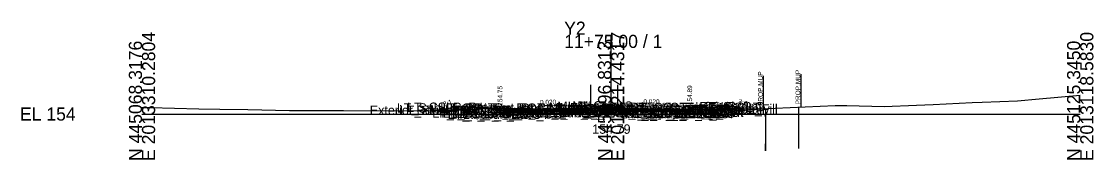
# Model space of a CAD drawing. Extents: x -26 to 203, y -10 to 6017.
# Drawn here: x -25.7 to 202.8, y 3490.3 to 3519.7 of the extents above; entities that cross this region are included whole.
import ezdxf

# ---------------------------------------------------------------- set-up
doc = ezdxf.new("R2010")
doc.units = 0
for name, color, linetype in [('Default', 7, 'Continuous'), ('Exist CMT Pavement', 7, 'Continuous'), ('Exist Cross Section Cell', 7, 'Continuous'), ('Exist XS Center Line Elevation Label', 7, 'Continuous'), ('Exist XS Ground Line', 7, 'Continuous'), ('Prop CMT Conc Surface', 7, 'Continuous'), ('Prop CMT Concrete Structures', 7, 'Continuous'), ('Prop CMT Pvmt Course 1', 7, 'Continuous'), ('Prop CMT Pvmt Course 1 CG', 7, 'Continuous'), ('Prop CMT Pvmt Course 1 Wedge', 7, 'Continuous'), ('Prop CMT Pvmt Course 2', 7, 'Continuous'), ('Prop CMT Pvmt Course 2 Wedge', 7, 'Continuous'), ('Prop CMT Pvmt Course 3', 7, 'Continuous'), ('Prop CMT Pvmt Surface', 7, 'Continuous'), ('Prop CMT Pvmt Wedge Surface 1', 7, 'Continuous'), ('Prop CMT Pvmt Wedge Surface 2', 7, 'Continuous'), ('Prop CMT Pvmt Wedge Surface 3', 7, 'Continuous'), ('Prop CMT Slope Grass', 7, 'Continuous'), ('Prop CMT Subgrade Earthwork', 7, 'Continuous'), ('Prop XS Earthwork Shape', 7, 'Continuous'), ('Prop XS Hydro Elevations', 7, 'Continuous'), ('Prop XS Label Text', 7, 'Continuous'), ('Prop XS SE Text', 7, 'Continuous'), ('Prop XS Side Slope Text', 7, 'Continuous'), ('Scratch_Level_0', 7, 'Continuous'), ('Scratch_Level_1', 7, 'Continuous'), ('Scratch_Level_3', 7, 'Continuous')]:
    doc.layers.add(name, color=color, linetype=linetype)

msp = doc.modelspace()

# ---------------------------------------------------------------- linework, layer by layer
at = {"layer": 'Exist CMT Pavement'}
msp.add_lwpolyline([(96.81, 3500.8), (100, 3500.79), (106.16, 3500.78), (106.96, 3500.77), (107.67, 3500.77), (113.75, 3500.75)], dxfattribs=at)
at = {"layer": 'Exist Cross Section Cell'}
for p, q in [((100, 3500), (100, 3516.87)), ((0, 3500), (100, 3500)), ((100, 3500), (200, 3500))]:
    msp.add_line(p, q, dxfattribs=at)
at = {"layer": 'Exist XS Ground Line'}
msp.add_lwpolyline([(0, 3501.37), (1.74, 3501.42), (12.12, 3501.1), (16.59, 3501.03), (22.55, 3500.95), (31.45, 3500.78), (32.99, 3500.74), (36.63, 3500.73), (41.86, 3500.72), (42.97, 3500.72), (54.75, 3500.66), (55.19, 3500.66), (61.72, 3500.74), (66.6, 3500.85), (74.03, 3501.16), (74.73, 3501.17), (82.07, 3501.15), (89, 3501.08), (92.28, 3501.08), (94.96, 3501.08), (95.27, 3501.03), (96.81, 3500.8), (100, 3500.79), (106.16, 3500.78), (106.96, 3500.77), (107.67, 3500.77), (116.6, 3500.73), (118.47, 3500.97), (119.47, 3500.97), (124.15, 3501.08), (130.91, 3501.08), (131.78, 3501.11), (147.77, 3501.82), (150.27, 3501.82), (158.2, 3501.62), (165.12, 3501.92), (168.63, 3502.05), (176.93, 3502.43), (179.07, 3502.52), (186.62, 3502.78), (191.27, 3503.25), (200, 3504.03)], dxfattribs=at)
at = {"layer": 'Prop CMT Conc Surface'}
for points in [[(76.33, 3500.75), (76.33, 3501.25), (75.83, 3501.25)], [(116.77, 3500.89), (116.77, 3501.39), (117.27, 3501.39)], [(78.33, 3500.87), (76.33, 3500.75)], [(114.77, 3501.01), (116.77, 3500.89)]]:
    msp.add_lwpolyline(points, dxfattribs=at)
at = {"layer": 'Prop CMT Concrete Structures'}
for p, q in [((95.72, 3501.38), (95.71, 3501.22)), ((96.47, 3501.63), (95.72, 3501.38)), ((98.91, 3501.73), (96.47, 3501.63)), ((100.7, 3501.69), (98.91, 3501.73)), ((101.45, 3501.44), (100.7, 3501.69)), ((101.46, 3501.27), (101.45, 3501.44))]:
    msp.add_line(p, q, dxfattribs=at)
for points in [[(78.33, 3500.87), (76.33, 3500.75), (76.33, 3501.25), (75.83, 3501.25)], [(75.83, 3501.25), (75.83, 3500.24), (78.33, 3500.29)], [(95.71, 3501.22), (101.46, 3501.27)], [(114.77, 3501.01), (116.77, 3500.89), (116.77, 3501.39), (117.27, 3501.39)], [(117.27, 3501.39), (117.27, 3500.38), (114.77, 3500.43)], [(78.33, 3500.29), (78.33, 3500.87)], [(114.77, 3500.43), (114.77, 3501.01)]]:
    msp.add_lwpolyline(points, dxfattribs=at)
at = {"layer": 'Prop CMT Pvmt Course 1'}
for points in [[(95.71, 3501.22), (78.33, 3500.87)], [(94.89, 3500.95), (94.89, 3501.2)], [(94.89, 3500.95), (94.89, 3501.2)], [(95.71, 3501.22), (101.46, 3501.27)], [(101.46, 3501.27), (114.77, 3501.01)], [(101.46, 3501.02), (101.46, 3501.27)], [(101.46, 3501.27), (101.46, 3501.02)], [(113.77, 3500.9), (101.46, 3501.15)], [(101.46, 3501.15), (101.46, 3501.02), (101.46, 3501.02)], [(78.33, 3500.62), (95.71, 3500.97)], [(78.33, 3500.87), (78.33, 3500.62)], [(94.96, 3501.08), (94.89, 3501.08)], [(94.89, 3501.08), (94.89, 3500.95), (94.89, 3500.95)], [(113.77, 3500.78), (113.77, 3500.9)], [(114.77, 3500.76), (113.77, 3500.78)], [(114.77, 3501.01), (114.77, 3500.76)]]:
    msp.add_lwpolyline(points, dxfattribs=at)
at = {"layer": 'Prop CMT Pvmt Course 1 CG'}
for points in [[(78.33, 3500.29), (75.33, 3500.23), (74.99, 3499.89)], [(74.99, 3499.89), (78.33, 3499.95)], [(78.33, 3500.04), (78.33, 3500.29)], [(114.77, 3500.43), (117.77, 3500.37), (118.11, 3500.03)], [(114.77, 3500.18), (114.77, 3500.43)], [(118.11, 3500.03), (114.77, 3500.09)]]:
    msp.add_lwpolyline(points, dxfattribs=at)
at = {"layer": 'Prop CMT Pvmt Course 1 Wedge'}
for points in [[(101.46, 3501.15), (106.16, 3501.06), (106.96, 3501.04), (107.67, 3501.03), (113.77, 3500.9)], [(101.46, 3501.02), (101.46, 3501.15)], [(113.77, 3500.78), (107.67, 3500.9), (106.96, 3500.91), (106.16, 3500.93), (101.46, 3501.02)], [(113.77, 3500.9), (113.77, 3500.78)]]:
    msp.add_lwpolyline(points, dxfattribs=at)
at = {"layer": 'Prop CMT Pvmt Course 2'}
for points in [[(95.71, 3500.97), (78.33, 3500.62)], [(78.33, 3500.29), (94.96, 3500.62)], [(78.33, 3500.62), (78.33, 3500.29)], [(94.89, 3500.62), (94.89, 3500.95)], [(101.46, 3501.02), (101.46, 3500.69)], [(113.77, 3500.45), (113.77, 3500.78)], [(113.77, 3500.78), (114.77, 3500.76)], [(114.77, 3500.43), (113.77, 3500.45)], [(114.77, 3500.76), (114.77, 3500.43)]]:
    msp.add_lwpolyline(points, dxfattribs=at)
at = {"layer": 'Prop CMT Pvmt Course 2 Wedge'}
for points in [[(101.46, 3501.02), (106.16, 3500.93), (106.96, 3500.91), (107.67, 3500.9), (113.77, 3500.78)], [(101.46, 3500.81), (101.46, 3501.02)], [(113.77, 3500.75), (107.67, 3500.77), (106.96, 3500.77), (106.16, 3500.78), (102.43, 3500.79)], [(113.77, 3500.78), (113.77, 3500.75)]]:
    msp.add_lwpolyline(points, dxfattribs=at)
at = {"layer": 'Prop CMT Pvmt Course 3'}
for points in [[(96.81, 3500.66), (78.33, 3500.29)], [(78.33, 3500.29), (78.33, 3499.95)], [(78.33, 3499.95), (94.96, 3500.29)], [(94.89, 3500.29), (94.89, 3500.62)], [(113.77, 3500.45), (114.77, 3500.43)], [(113.77, 3500.11), (113.77, 3500.45)], [(114.77, 3500.09), (113.77, 3500.11)], [(114.77, 3500.43), (114.77, 3500.09)]]:
    msp.add_lwpolyline(points, dxfattribs=at)
at = {"layer": 'Prop CMT Pvmt Surface'}
for points in [[(95.71, 3501.22), (78.33, 3500.87)], [(95.71, 3501.22), (101.46, 3501.27)], [(101.46, 3501.27), (114.77, 3501.01)]]:
    msp.add_lwpolyline(points, dxfattribs=at)
at = {"layer": 'Prop CMT Pvmt Wedge Surface 1'}
for points in [[(101.46, 3501.27), (101.46, 3501.02), (101.46, 3501.02), (101.46, 3501.15)], [(101.46, 3501.15), (113.77, 3500.9)], [(113.77, 3500.9), (113.77, 3500.78)], [(113.77, 3500.78), (114.77, 3500.76)], [(114.77, 3500.76), (114.77, 3501.01)]]:
    msp.add_lwpolyline(points, dxfattribs=at)
at = {"layer": 'Prop CMT Pvmt Wedge Surface 2'}
for points in [[(101.46, 3501.27), (101.46, 3501.02)], [(101.46, 3501.02), (114.77, 3500.76)], [(114.77, 3500.76), (114.77, 3501.01)]]:
    msp.add_lwpolyline(points, dxfattribs=at)
at = {"layer": 'Prop CMT Pvmt Wedge Surface 3'}
for points in [[(101.46, 3501.27), (101.46, 3500.69)], [(96.81, 3500.66), (101.46, 3500.69)], [(101.46, 3500.69), (114.77, 3500.43)], [(114.77, 3500.43), (114.77, 3501.01)]]:
    msp.add_lwpolyline(points, dxfattribs=at)
at = {"layer": 'Prop CMT Slope Grass'}
for points in [[(75.83, 3501.25), (66.33, 3501.44), (64.42, 3500.8)], [(117.27, 3501.39), (126.27, 3501.57)], [(126.27, 3501.57), (126.77, 3501.58), (128.25, 3501.08)]]:
    msp.add_lwpolyline(points, dxfattribs=at)
at = {"layer": 'Prop CMT Subgrade Earthwork'}
msp.add_line((96.81, 3500.8), (96.81, 3500.32), dxfattribs=at)
for points in [[(78.33, 3499.95), (74.99, 3499.89), (73.58, 3501.3)], [(114.77, 3500.09), (118.11, 3500.03), (119.51, 3501.43)], [(96.81, 3500.32), (78.33, 3499.95)], [(113.77, 3500.11), (113.75, 3500.75)], [(113.77, 3500.11), (114.77, 3500.09)]]:
    msp.add_lwpolyline(points, dxfattribs=at)
at = {"layer": 'Prop XS Earthwork Shape'}
for points in [[(66.6, 3500.85), (73.73, 3501.15), (73.58, 3501.3), (66.33, 3501.44), (64.42, 3500.8)], [(66.6, 3500.85), (73.73, 3501.15), (73.58, 3501.3), (66.33, 3501.44), (64.42, 3500.8)], [(66.6, 3500.85), (73.73, 3501.15), (73.58, 3501.3), (66.33, 3501.44), (64.42, 3500.8)], [(66.6, 3500.85), (73.73, 3501.15), (73.58, 3501.3), (66.33, 3501.44), (64.42, 3500.8)], [(73.73, 3501.15), (74.03, 3501.16), (74.73, 3501.17), (75.83, 3501.16), (75.83, 3500.24), (78.33, 3500.29), (78.33, 3500.87), (89.04, 3501.08), (92.28, 3501.08), (94.96, 3501.08), (95.27, 3501.03), (96.81, 3500.8), (96.81, 3500.32), (78.33, 3499.95), (74.99, 3499.89)], [(96.81, 3500.32), (78.33, 3499.95), (74.99, 3499.89), (73.73, 3501.15), (74.03, 3501.16), (74.73, 3501.17), (75.83, 3501.16), (75.83, 3500.24), (78.33, 3500.29), (78.33, 3500.87), (89.04, 3501.08), (92.28, 3501.08), (94.96, 3501.08), (95.27, 3501.03), (96.81, 3500.8)], [(96.81, 3500.32), (78.33, 3499.95), (74.99, 3499.89), (73.73, 3501.15), (74.03, 3501.16), (74.73, 3501.17), (75.83, 3501.16), (75.83, 3500.24), (78.33, 3500.29), (78.33, 3500.87), (89.04, 3501.08), (92.28, 3501.08), (94.96, 3501.08), (95.27, 3501.03), (96.81, 3500.8)], [(96.81, 3500.32), (78.33, 3499.95), (74.99, 3499.89), (73.73, 3501.15), (74.03, 3501.16), (74.73, 3501.17), (75.83, 3501.16), (75.83, 3500.24), (78.33, 3500.29), (78.33, 3500.87), (89.04, 3501.08), (92.28, 3501.08), (94.96, 3501.08), (95.27, 3501.03), (96.81, 3500.8)], [(76.33, 3500.75), (76.33, 3501.16), (75.83, 3501.16), (75.83, 3500.24), (78.33, 3500.29), (78.33, 3500.87)], [(76.33, 3500.75), (76.33, 3501.16), (75.83, 3501.16), (75.83, 3500.24), (78.33, 3500.29), (78.33, 3500.87)], [(76.33, 3500.75), (76.33, 3501.16), (75.83, 3501.16), (75.83, 3500.24), (78.33, 3500.29), (78.33, 3500.87)], [(76.33, 3500.75), (76.33, 3501.16), (75.83, 3501.16), (75.83, 3500.24), (78.33, 3500.29), (78.33, 3500.87)], [(76.33, 3500.75), (76.33, 3501.16), (82.07, 3501.15), (89, 3501.08), (89.04, 3501.08), (78.33, 3500.87)], [(76.33, 3500.75), (76.33, 3501.16), (82.07, 3501.15), (89, 3501.08), (89.04, 3501.08), (78.33, 3500.87)], [(76.33, 3500.75), (76.33, 3501.16), (82.07, 3501.15), (89, 3501.08), (89.04, 3501.08), (78.33, 3500.87)], [(76.33, 3500.75), (76.33, 3501.16), (82.07, 3501.15), (89, 3501.08), (89.04, 3501.08), (78.33, 3500.87)], [(119.05, 3500.97), (119.51, 3501.43), (126.27, 3501.57), (126.77, 3501.58), (128.25, 3501.08), (124.15, 3501.08), (119.47, 3500.97)], [(119.05, 3500.97), (119.51, 3501.43), (126.27, 3501.57), (126.77, 3501.58), (128.25, 3501.08), (124.15, 3501.08), (119.47, 3500.97)], [(119.05, 3500.97), (119.51, 3501.43), (126.27, 3501.57), (126.77, 3501.58), (128.25, 3501.08), (124.15, 3501.08), (119.47, 3500.97)], [(119.05, 3500.97), (119.51, 3501.43), (126.27, 3501.57), (126.77, 3501.58), (128.25, 3501.08), (124.15, 3501.08), (119.47, 3500.97)], [(113.77, 3500.11), (114.77, 3500.09), (118.11, 3500.03), (119.05, 3500.97), (118.47, 3500.97), (117.27, 3500.82), (117.27, 3500.38), (114.77, 3500.43), (114.77, 3500.74), (113.75, 3500.75)], [(113.77, 3500.11), (114.77, 3500.09), (118.11, 3500.03), (119.05, 3500.97), (118.47, 3500.97), (117.27, 3500.82), (117.27, 3500.38), (114.77, 3500.43), (114.77, 3500.74), (113.75, 3500.75)], [(113.77, 3500.11), (114.77, 3500.09), (118.11, 3500.03), (119.05, 3500.97), (118.47, 3500.97), (117.27, 3500.82), (117.27, 3500.38), (114.77, 3500.43), (114.77, 3500.74), (113.75, 3500.75)], [(113.77, 3500.11), (114.77, 3500.09), (118.11, 3500.03), (119.05, 3500.97), (118.47, 3500.97), (117.27, 3500.82), (117.27, 3500.38), (114.77, 3500.43), (114.77, 3500.74), (113.75, 3500.75)], [(117.27, 3500.82), (117.27, 3500.38), (114.77, 3500.43), (114.77, 3500.74), (116.6, 3500.73)], [(117.27, 3500.82), (117.27, 3500.38), (114.77, 3500.43), (114.77, 3500.74), (116.6, 3500.73)], [(114.77, 3500.74), (116.6, 3500.73), (117.27, 3500.82), (117.27, 3500.38), (114.77, 3500.43)], [(117.27, 3500.82), (117.27, 3500.38), (114.77, 3500.43), (114.77, 3500.74), (116.6, 3500.73)]]:
    msp.add_lwpolyline(points, close=True, dxfattribs=at)
at = {"layer": 'Prop XS Label Text'}
for p, q in [((132.42, 3508.14), (132.42, 3501.14)), ((140.42, 3508.49), (140.42, 3501.49))]:
    msp.add_line(p, q, dxfattribs=at)
at = {"layer": 'Scratch_Level_1'}
for p, q in [((132.92, 3501.16), (132.92, 3492.18)), ((139.92, 3501.47), (139.92, 3492.63)), ((132.92, 3492.18), (132.92, 3493.64))]:
    msp.add_line(p, q, dxfattribs=at)
at = {"layer": 'Scratch_Level_3'}
for p, q in [((95.71, 3501.22), (95.71, 3506.25)), ((101.46, 3501.27), (101.46, 3506.25))]:
    msp.add_line(p, q, dxfattribs=at)

# ---------------------------------------------------------------- texts
at = {"layer": 'Default'}
msp.add_text('-', height=0.0001, dxfattribs=at).set_placement((0, 3500))
at = {"layer": 'Exist Cross Section Cell'}
for s, p in [('Y2', (90, 3516.87)), ('11+75.00 / 1', (90, 3514.07)), ('EL 154', (-26, 3498.6))]:
    msp.add_text(s, height=2.8, dxfattribs=at).set_placement(p)
for s, p in [('E 2013310.2804', (2.8, 3490)), ('E 2013214.4317', (102.8, 3490)), ('E 2013118.5830', (202.8, 3490)), ('N 445068.3176', (0, 3490)), ('N 445096.8313', (100, 3490)), ('N 445125.3450', (200, 3490))]:
    msp.add_text(s, height=2.8, rotation=90, dxfattribs=at).set_placement(p)
at = {"layer": 'Exist XS Center Line Elevation Label'}
msp.add_text('154.79', height=2, dxfattribs=at).set_placement((95.97, 3495.79))
at = {"layer": 'Prop XS Hydro Elevations'}
for s, p in [('154.75', (76.83, 3501.75)), ('154.89', (117.27, 3501.89))]:
    msp.add_text(s, height=1, rotation=90, dxfattribs=at).set_placement(p)
at = {"layer": 'Prop XS Label Text'}
for p in [(132.32, 3501.71), (140.32, 3502.06)]:
    msp.add_text('PROP.MUP', height=1, rotation=90, dxfattribs=at).set_placement(p)
at = {"layer": 'Prop XS SE Text'}
for rotation, p in [(1.1458, (84.84, 3502)), (358.8542, (106.87, 3502.17))]:
    msp.add_text('0.020', height=1, rotation=rotation, dxfattribs=at).set_placement(p)
at = {"layer": 'Prop XS Side Slope Text'}
for rotation, p in [(18.4349, (64.38, 3501.58)), (341.5651, (127, 3502.29))]:
    msp.add_text('3:1', height=1, rotation=rotation, dxfattribs=at).set_placement(p)
at = {"layer": 'Scratch_Level_0'}
for s, p in [('Exterior Boundary', (48.56, 3499.8)), ('LT_Sub_Trench_Out_DLT', (54.32, 3500.29)), ('LT_Slope_Fill', (54.94, 3499.8)), ('LT_CSLP_Pnt', (56.5, 3500.44)), ('LT_CG1_Shelf_Out', (61.88, 3499.23)), ('LT_CG_Top_Face', (63.59, 3500.25)), ('LT_CG_Top_BOC', (64.11, 3500.25)), ('LT_CG_Bot_BOC', (64.14, 3499.24)), ('LT_CG_Top_Gut', (64.56, 3499.75)), ('LT_Sub_OEOT_CG', (65.7, 3499.04)), ('LT_CG_Bot_IE', (68.24, 3499.29)), ('LT_PV2_OEOT', (68.5, 3499.62)), ('LT_PV3_OEOT', (68.5, 3499.29)), ('LT_PV1_OEOT', (69.07, 3499.87)), ('LT_Sub_OEEOP', (84.17, 3499.29)), ('LT_PV2_OEEOP', (84.27, 3499.95)), ('LT_PV3_OEEOP', (84.27, 3499.62)), ('LT_PV1_OEEOP', (84.84, 3500.08)), ('LT_PV2_IEEOP', (84.85, 3499.95)), ('LT_PV1_IEEOP', (85.41, 3500.08)), ('LT_PV2_PGL1', (85.77, 3499.95)), ('LT_PV3_PGL1', (85.77, 3499.62)), ('LT_PV2_PGL', (86.11, 3499.95)), ('LT_PV4_PGL', (86.11, 3499.29)), ('LT_PV1_PGL', (86.67, 3500.2)), ('MI_Face In', (86.79, 3500.37)), ('MI_Top In', (88.5, 3500.62)), ('RT_PV_IEEOP_EG', (90.57, 3499.79)), ('MI_Crown', (91.73, 3500.73)), ('RT_PV2_IEEOP', (92.34, 3500.01)), ('RT_PV3_IEEOP', (92.34, 3499.67)), ('MI_Face Out', (92.69, 3500.42)), ('MI_Top Out', (92.9, 3500.67)), ('RT_PV1_IEEOP', (92.9, 3500.13)), ('RT_PV2_PGL1', (93.27, 3500.01)), ('RT_PV3_PGL1', (93.27, 3499.67)), ('RT_PV2_PGL', (93.6, 3500.01)), ('RT_PV3_PGL', (93.6, 3499.67)), ('RT_PV4_PGL', (93.6, 3499.34)), ('MI_Bot Out', (93.69, 3500.26)), ('RT_PV1_PGL', (94.16, 3500.26)), ('RT_PV_EG_TestPt', (94.46, 3499.77)), ('RT_PV_Sub_Tie_Out', (98.65, 3499.75)), ('RT_Sub_Trench_Out_DLT', (99.86, 3500.43)), ('RT_PV_OEEOP_EG', (101.26, 3499.75)), ('RT_Sub_OEOT_CG', (102.09, 3499.18)), ('RT_Sub_OEEOP', (102.93, 3499.11)), ('RT_PV2_OEEOP', (103.02, 3499.78)), ('RT_PV3_OEEOP', (103.02, 3499.45)), ('RT_PV1_OEEOP', (103.59, 3499.9)), ('RT_CG_Top_Face', (103.98, 3500.39)), ('RT_CG1_Shelf_Out', (104.27, 3499.37)), ('RT_CG_Bot_IE', (104.63, 3499.43)), ('RT_Sub_OEOT', (104.8, 3499.09)), ('RT_PV2_OEOT', (104.89, 3499.76)), ('RT_PV3_OEOT', (104.89, 3499.43)), ('RT_CG_Top_Gut', (104.95, 3499.89)), ('RT_PV1_OEOT', (105.46, 3500.01)), ('RT_CG_Top_BOC', (105.5, 3500.39)), ('RT_CG_Bot_BOC', (105.53, 3499.38)), ('RT_Sub_OEOP', (108.08, 3499.11)), ('Exterior Boundary', (112.4, 3500.08)), ('RT_Slope_Fill', (118.73, 3500.08)), ('RT_Shld_O', (118.8, 3500.57)), ('CSLP_Pnt', (119.63, 3500.58)), ('LT_Sub_OEOP', (65.18, 3498.97)), ('LT_Sub_OEOT', (68.41, 3498.95))]:
    msp.add_text(s, height=2, dxfattribs=at).set_placement(p)

doc.saveas('drawing.dxf')
